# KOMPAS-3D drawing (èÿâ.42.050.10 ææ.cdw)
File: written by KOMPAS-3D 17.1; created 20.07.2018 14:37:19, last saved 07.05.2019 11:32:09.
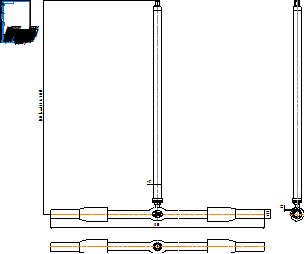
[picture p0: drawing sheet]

Sheet 1: A4, portrait

Title block, sheet 1: name: КШГ.42.050.10 СС; material: Внимание! Данный продукт является объектом авторского права ООО «Торговый Дом АДЛ». / Запрещается изменение, копирование, распространение / (в том числе путем копирования на другие сайты и ресурсы в Интернете) / или любое иное использование информации и объектов без предварительного / согласия правообладателя (ООО «Торговый Дом АДЛ»).; sheets: 1; organisation: ООО "Торговый дом АДЛ"; sheet format: A4; stored path: C:\Users\tra\Desktop\2д чертежи\Шаровые краны БИВАЛ\КШ_Бивал_серия_42_52\KOMPAS 2D\КШГ.42.050.10 СС.cdw

Views: Вид 1, Проекционный вид 2, Проекционный вид 3
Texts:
  kka
  adl
  (от 250 до 5000)
Dimensions and other numbers on the sheet: 1500; 57; 63; 5,8; 1:1; 1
